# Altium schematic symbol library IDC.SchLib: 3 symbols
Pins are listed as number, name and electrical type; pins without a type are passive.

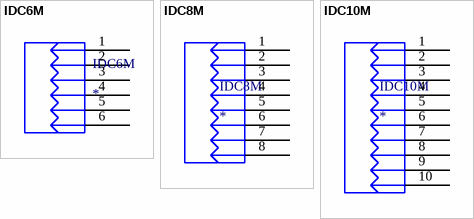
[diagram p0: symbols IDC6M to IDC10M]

## IDC6M
designator IDC6M
IDC6M
footprint IDC6M
pins: 1, 2, 3, 4, 5, 6

## IDC8M
designator IDC8M
IDC8M
footprint IDC8M
pins: 1, 2, 3, 4, 5, 6, 7, 8

## IDC10M
designator IDC10M
IDC10M
footprint IDC10M
pins: 1, 2, 3, 4, 5, 6, 7, 8, 9, 10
